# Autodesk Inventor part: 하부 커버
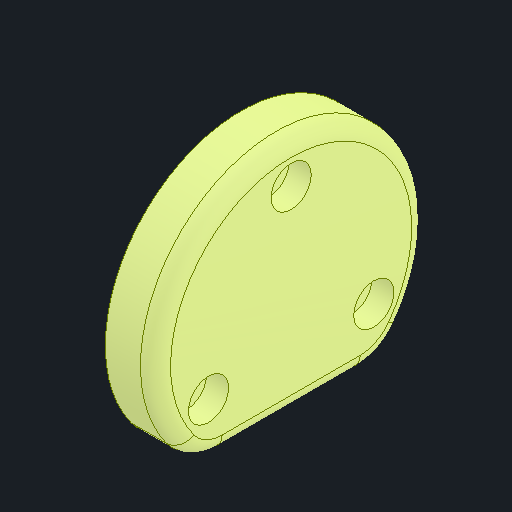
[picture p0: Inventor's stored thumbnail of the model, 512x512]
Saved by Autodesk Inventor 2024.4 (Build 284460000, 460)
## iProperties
Created: 2026-03
Part Number: 하부 커버
Material: 알루미늄 6061
Document SubType Name: Modeling
Designer: user
Density: 2.7 g/cm^3
Appearance: 기본값
Author: jhkim
Sending System: Autodesk Inventor 2026
Preprocessor: ST-DEVELOPER v20.1
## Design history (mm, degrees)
feature "솔리드1"
node "솔리드2"
